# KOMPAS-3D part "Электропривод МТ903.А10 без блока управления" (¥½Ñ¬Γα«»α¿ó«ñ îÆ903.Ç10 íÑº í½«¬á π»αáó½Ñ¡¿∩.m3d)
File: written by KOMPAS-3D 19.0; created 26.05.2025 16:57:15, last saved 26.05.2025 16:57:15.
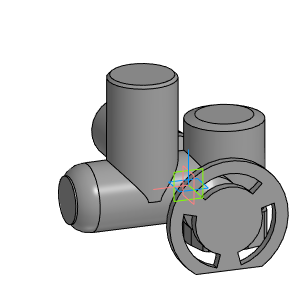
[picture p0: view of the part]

Document properties: Полное имя файла: E:\Dendor Работа Сачек\3D для проекитирвщиков\3.4 Электропривод МТ903.А\stp_Тип МТ903.А без блока управления\Электропривод МТ903.А10 без блока управления.m3d

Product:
- Part/product: Электропривод МТ903.А10 без блока управления

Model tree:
1. Операция без истории:1  (labels: Электропривод МТ903.А10 без блока управления)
